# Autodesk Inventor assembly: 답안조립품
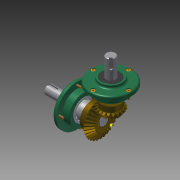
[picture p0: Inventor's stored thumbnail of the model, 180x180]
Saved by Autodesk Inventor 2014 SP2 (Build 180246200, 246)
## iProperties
Created: 2016-04
Part Number: 답안조립품
Document SubType Name: Assembly
Designer: 201-25
Author: 201-25
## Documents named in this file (14)
- C:\Users\201-25\Desktop\460407V1011\답안조립품.iam
- C:\Users\201-25\Desktop\460407V1011\본체.ipt
- C:\Users\201-25\Desktop\460407V1011\커버.ipt
- C:\Users\201-25\Desktop\460407V1011\오일실 17 32 8.ipt
- C:\Users\201-25\Desktop\460407V1011\서브 축.ipt
- 서브 축.ipt
- C:\Users\201-25\Desktop\460407V1011\메인 축.ipt
- 메인 축.ipt
- C:\Users\201-25\Desktop\460407V1011\베어링 6203.ipt
- C:\Users\201-25\Desktop\460407V1011\키 4x4.ipt
- C:\Users\201-25\Desktop\460407V1011\키 5x5.ipt
- C:\Users\201-25\Desktop\460407V1011\M4.ipt
- C:\Users\201-25\Desktop\460407V1011\메인 베벨기어.ipt
- C:\Users\201-25\Desktop\460407V1011\서브 베벨기어.ipt
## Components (8 placed, 1 different names)
1. M4:1
2. M4:2
3. M4:3
4. M4:4
5. M4:5
6. M4:6
7. M4:7
8. M4:8
